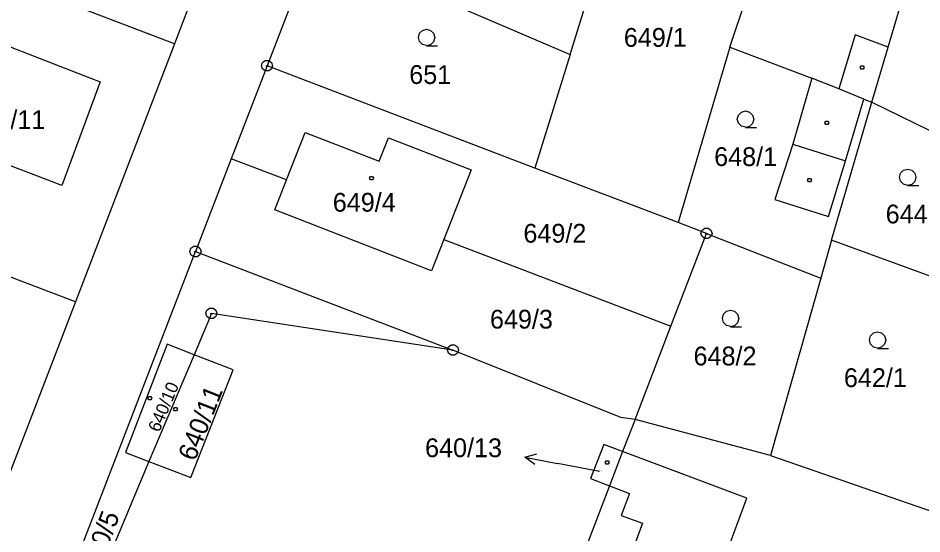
# Model space of a CAD drawing. Extents: x -759060 to -757386, y -1172273 to -1170948.
# Drawn here: x -758121.7 to -758040, y -1171296.1 to -1171249.4 of the extents above; entities that cross this region are included whole.
import ezdxf

# ---------------------------------------------------------------- set-up
doc = ezdxf.new("R2010")
doc.units = 0
for name, color, linetype in [('Vrstva 1', 7, 'Continuous'), ('Vrstva 12', 7, 'Continuous'), ('Vrstva 2', 7, 'Continuous'), ('Vrstva 3', 7, 'Continuous'), ('Vrstva 4', 7, 'Continuous'), ('Vrstva 5', 7, 'Continuous'), ('Vrstva 7', 7, 'Continuous'), ('Vrstva 8', 7, 'Continuous')]:
    doc.layers.add(name, color=color, linetype=linetype)

msp = doc.modelspace()

# ---------------------------------------------------------------- linework, layer by layer
at = {"layer": 'Vrstva 1'}
for p, q in [((-758084.37, -1171215.28), (-758099.2, -1171253.75)), ((-758071.82, -1171252.72), (-758063.29, -1171225.21)), ((-758098.72, -1171228.44), (-758107.56, -1171251.77)), ((-758043.08, -1171252.05), (-758039.35, -1171239.51)), ((-758107.56, -1171251.77), (-758135.53, -1171241.06)), ((-758057.4, -1171252.05), (-758054.82, -1171244.39)), ((-758090.57, -1171244.68), (-758071.82, -1171252.72)), ((-758107.56, -1171251.77), (-758116.52, -1171275.1)), ((-758122.42, -1171252.04), (-758115.22, -1171254.83)), ((-758071.82, -1171252.72), (-758075, -1171262.99)), ((-758057.4, -1171252.05), (-758062.05, -1171267.93)), ((-758057.4, -1171252.05), (-758049.98, -1171254.87)), ((-758044.56, -1171257.04), (-758043.08, -1171252.05)), ((-758099.2, -1171253.75), (-758102.44, -1171262.15)), ((-758075, -1171262.99), (-758099.2, -1171253.75)), ((-758114.28, -1171255.19), (-758117.74, -1171264.58)), ((-758115.22, -1171254.83), (-758114.28, -1171255.19)), ((-758049.98, -1171254.87), (-758051.7, -1171260.84)), ((-758046.92, -1171262.34), (-758045.28, -1171256.75)), ((-758045.28, -1171256.75), (-758044.56, -1171257.04)), ((-758048.21, -1171269.53), (-758044.56, -1171257.04)), ((-758044.56, -1171257.04), (-758033.42, -1171262.46)), ((-758118.67, -1171264.22), (-758130.07, -1171259.83)), ((-758097.44, -1171264.06), (-758095.77, -1171259.77)), ((-758095.77, -1171259.77), (-758089.07, -1171262.37)), ((-758089.07, -1171262.37), (-758088.24, -1171260.25)), ((-758088.24, -1171260.25), (-758080.77, -1171263.14)), ((-758051.7, -1171260.84), (-758053.32, -1171265.85)), ((-758102.44, -1171262.15), (-758105.67, -1171270.55)), ((-758097.44, -1171264.06), (-758102.44, -1171262.15)), ((-758048.46, -1171267.39), (-758046.92, -1171262.34)), ((-758080.77, -1171263.14), (-758083.24, -1171269.47)), ((-758062.05, -1171267.93), (-758075, -1171262.99)), ((-758117.74, -1171264.58), (-758118.67, -1171264.22)), ((-758098.49, -1171266.76), (-758097.44, -1171264.06)), ((-758116.52, -1171275.1), (-758144.5, -1171264.39)), ((-758053.32, -1171265.85), (-758048.46, -1171267.39)), ((-758084.33, -1171272.28), (-758098.49, -1171266.76)), ((-758059.49, -1171268.91), (-758062.05, -1171267.93)), ((-758062.71, -1171277.3), (-758059.49, -1171268.91)), ((-758059.49, -1171268.91), (-758049.17, -1171272.94)), ((-758083.24, -1171269.47), (-758084.33, -1171272.28)), ((-758083.24, -1171269.47), (-758062.71, -1171277.3)), ((-758048.21, -1171269.53), (-758049.17, -1171272.94)), ((-758037.2, -1171273.53), (-758048.21, -1171269.53)), ((-758118.62, -1171304.17), (-758105.67, -1171270.55)), ((-758105.67, -1171270.55), (-758082.4, -1171279.45)), ((-758049.17, -1171272.94), (-758053.7, -1171288.99)), ((-758116.52, -1171275.1), (-758125.5, -1171298.45)), ((-758104.23, -1171276.14), (-758105.8, -1171279.87)), ((-758082.4, -1171279.45), (-758104.23, -1171276.14)), ((-758065.95, -1171285.74), (-758062.71, -1171277.3)), ((-758108.22, -1171278.93), (-758112, -1171288.71)), ((-758105.8, -1171279.87), (-758108.22, -1171278.93)), ((-758067.22, -1171285.56), (-758082.4, -1171279.45)), ((-758105.8, -1171279.87), (-758109.87, -1171289.53)), ((-758102.26, -1171281.24), (-758105.8, -1171279.87)), ((-758106.09, -1171290.99), (-758102.26, -1171281.24)), ((-758065.95, -1171285.74), (-758067.22, -1171285.56)), ((-758065.95, -1171285.74), (-758067.07, -1171288.64)), ((-758053.7, -1171288.99), (-758065.95, -1171285.74)), ((-758112, -1171288.71), (-758109.87, -1171289.53)), ((-758068.78, -1171287.99), (-758069.97, -1171291.07)), ((-758067.07, -1171288.64), (-758068.78, -1171287.99)), ((-758067.07, -1171288.64), (-758068.26, -1171291.73)), ((-758055.84, -1171292.86), (-758067.07, -1171288.64)), ((-758109.87, -1171289.53), (-758115.76, -1171303.61)), ((-758109.87, -1171289.53), (-758106.09, -1171290.99)), ((-758053.7, -1171288.99), (-758017.68, -1171301.49)), ((-758069.97, -1171291.07), (-758068.26, -1171291.73)), ((-758068.26, -1171291.73), (-758070.29, -1171297.01)), ((-758066.98, -1171322.4), (-758055.84, -1171292.86))]:
    msp.add_line(p, q, dxfattribs=at)
at = {"layer": 'Vrstva 12'}
for p, q in [((-758122.42, -1171252.04), (-758115.22, -1171254.83)), ((-758114.28, -1171255.19), (-758117.74, -1171264.58)), ((-758115.22, -1171254.83), (-758114.28, -1171255.19)), ((-758118.67, -1171264.22), (-758130.07, -1171259.83)), ((-758097.44, -1171264.06), (-758095.77, -1171259.77)), ((-758095.77, -1171259.77), (-758089.07, -1171262.37)), ((-758089.07, -1171262.37), (-758088.24, -1171260.25)), ((-758088.24, -1171260.25), (-758080.77, -1171263.14)), ((-758080.77, -1171263.14), (-758083.24, -1171269.47)), ((-758117.74, -1171264.58), (-758118.67, -1171264.22)), ((-758098.49, -1171266.76), (-758097.44, -1171264.06)), ((-758084.33, -1171272.28), (-758098.49, -1171266.76)), ((-758083.24, -1171269.47), (-758084.33, -1171272.28)), ((-758108.22, -1171278.93), (-758112, -1171288.71)), ((-758105.8, -1171279.87), (-758108.22, -1171278.93)), ((-758102.26, -1171281.24), (-758105.8, -1171279.87)), ((-758106.09, -1171290.99), (-758102.26, -1171281.24)), ((-758112, -1171288.71), (-758109.87, -1171289.53)), ((-758068.78, -1171287.99), (-758069.97, -1171291.07)), ((-758067.07, -1171288.64), (-758068.78, -1171287.99)), ((-758055.84, -1171292.86), (-758067.07, -1171288.64)), ((-758109.87, -1171289.53), (-758106.09, -1171290.99)), ((-758069.97, -1171291.07), (-758068.26, -1171291.73)), ((-758068.26, -1171291.73), (-758066.46, -1171292.41)), ((-758066.46, -1171292.41), (-758067.21, -1171294.4)), ((-758066.98, -1171322.4), (-758055.84, -1171292.86)), ((-758067.21, -1171294.4), (-758065.27, -1171295.12)), ((-758065.27, -1171295.12), (-758068.76, -1171304.43))]:
    msp.add_line(p, q, dxfattribs=at)
at = {"layer": 'Vrstva 3'}
for points in [[(-758084.78, -1171251.92), (-758085.16, -1171251.82), (-758085.43, -1171251.55), (-758085.53, -1171251.18), (-758085.43, -1171250.81), (-758085.16, -1171250.54), (-758084.79, -1171250.44), (-758084.42, -1171250.54), (-758084.15, -1171250.81), (-758084.05, -1171251.19), (-758084.15, -1171251.57), (-758084.42, -1171251.84), (-758084.8, -1171251.94), (-758083.8, -1171251.94)], [(-758055.96, -1171259.31), (-758056.34, -1171259.21), (-758056.61, -1171258.94), (-758056.71, -1171258.57), (-758056.61, -1171258.2), (-758056.34, -1171257.93), (-758055.97, -1171257.83), (-758055.6, -1171257.93), (-758055.33, -1171258.2), (-758055.23, -1171258.58), (-758055.33, -1171258.96), (-758055.6, -1171259.23), (-758055.98, -1171259.33), (-758054.98, -1171259.33)], [(-758041.3, -1171264.56), (-758041.68, -1171264.46), (-758041.95, -1171264.19), (-758042.05, -1171263.82), (-758041.95, -1171263.45), (-758041.68, -1171263.18), (-758041.31, -1171263.08), (-758040.94, -1171263.18), (-758040.67, -1171263.45), (-758040.57, -1171263.83), (-758040.67, -1171264.21), (-758040.94, -1171264.48), (-758041.32, -1171264.58), (-758040.32, -1171264.58)], [(-758057.31, -1171277.33), (-758057.69, -1171277.23), (-758057.96, -1171276.96), (-758058.06, -1171276.59), (-758057.96, -1171276.22), (-758057.69, -1171275.95), (-758057.32, -1171275.85), (-758056.95, -1171275.95), (-758056.68, -1171276.22), (-758056.58, -1171276.6), (-758056.68, -1171276.98), (-758056.95, -1171277.25), (-758057.33, -1171277.35), (-758056.33, -1171277.35)], [(-758044.03, -1171279.28), (-758044.41, -1171279.18), (-758044.68, -1171278.91), (-758044.78, -1171278.54), (-758044.68, -1171278.17), (-758044.41, -1171277.9), (-758044.04, -1171277.8), (-758043.67, -1171277.9), (-758043.4, -1171278.17), (-758043.3, -1171278.55), (-758043.4, -1171278.93), (-758043.67, -1171279.2), (-758044.05, -1171279.3), (-758043.05, -1171279.3)]]:
    msp.add_lwpolyline(points, dxfattribs=at)
at = {"layer": 'Vrstva 4'}
for p, q in [((-758046.06, -1171250.96), (-758047.55, -1171255.84)), ((-758043.08, -1171252.05), (-758046.06, -1171250.96)), ((-758047.55, -1171255.84), (-758049.98, -1171254.87)), ((-758045.28, -1171256.75), (-758047.55, -1171255.84)), ((-758051.7, -1171260.84), (-758046.92, -1171262.34)), ((-758068.26, -1171291.73), (-758066.46, -1171292.41)), ((-758066.46, -1171292.41), (-758067.21, -1171294.4)), ((-758067.21, -1171294.4), (-758065.27, -1171295.12)), ((-758065.27, -1171295.12), (-758068.76, -1171304.43))]:
    msp.add_line(p, q, dxfattribs=at)
at = {"layer": 'Vrstva 5'}
for points in [[(-758045.35, -1171253.74), (-758045.26, -1171253.89), (-758045.35, -1171254.04), (-758045.53, -1171254.04), (-758045.62, -1171253.89), (-758045.53, -1171253.74)], [(-758048.54, -1171258.76), (-758048.45, -1171258.91), (-758048.54, -1171259.06), (-758048.72, -1171259.06), (-758048.81, -1171258.91), (-758048.72, -1171258.76)], [(-758089.66, -1171263.75), (-758089.57, -1171263.9), (-758089.66, -1171264.05), (-758089.84, -1171264.05), (-758089.93, -1171263.9), (-758089.84, -1171263.75)], [(-758050.1, -1171263.94), (-758050.01, -1171264.09), (-758050.1, -1171264.24), (-758050.28, -1171264.24), (-758050.37, -1171264.09), (-758050.28, -1171263.94)], [(-758109.71, -1171283.65), (-758109.62, -1171283.8), (-758109.71, -1171283.95), (-758109.89, -1171283.95), (-758109.98, -1171283.8), (-758109.89, -1171283.65)], [(-758107.39, -1171284.64), (-758107.3, -1171284.79), (-758107.39, -1171284.94), (-758107.57, -1171284.94), (-758107.66, -1171284.79), (-758107.57, -1171284.64)], [(-758068.37, -1171289.46), (-758068.28, -1171289.61), (-758068.37, -1171289.76), (-758068.55, -1171289.76), (-758068.64, -1171289.61), (-758068.55, -1171289.46)]]:
    msp.add_lwpolyline(points, close=True, dxfattribs=at)
at = {"layer": 'Vrstva 7'}
for p in [(-758075.907, -1171289.137), (-758069.16, -1171290.43)]:
    msp.add_line(p, (-758072.96, -1171289.7), dxfattribs=at)
msp.add_lwpolyline([(-758075.018, -1171289.816), (-758075.907, -1171289.137), (-758074.831, -1171288.834)], dxfattribs=at)
at = {"layer": 'Vrstva 8'}
for p, q in [((-758099.32, -1171253.75), (-758099.08, -1171253.75)), ((-758059.61, -1171268.91), (-758059.37, -1171268.91)), ((-758105.79, -1171270.55), (-758105.55, -1171270.55)), ((-758104.35, -1171276.14), (-758104.11, -1171276.14)), ((-758082.52, -1171279.45), (-758082.28, -1171279.45))]:
    msp.add_line(p, q, dxfattribs=at)
for points in [[(-758099.05, -1171253.27), (-758098.8, -1171253.45), (-758098.7, -1171253.74), (-758098.8, -1171254.03), (-758099.05, -1171254.21), (-758099.36, -1171254.21), (-758099.61, -1171254.03), (-758099.71, -1171253.74), (-758099.61, -1171253.45), (-758099.36, -1171253.27)], [(-758059.34, -1171268.43), (-758059.09, -1171268.61), (-758058.99, -1171268.9), (-758059.09, -1171269.19), (-758059.34, -1171269.37), (-758059.65, -1171269.37), (-758059.9, -1171269.19), (-758060, -1171268.9), (-758059.9, -1171268.61), (-758059.65, -1171268.43)], [(-758105.52, -1171270.07), (-758105.27, -1171270.25), (-758105.17, -1171270.54), (-758105.27, -1171270.83), (-758105.52, -1171271.01), (-758105.83, -1171271.01), (-758106.08, -1171270.83), (-758106.18, -1171270.54), (-758106.08, -1171270.25), (-758105.83, -1171270.07)], [(-758104.08, -1171275.66), (-758103.83, -1171275.84), (-758103.73, -1171276.13), (-758103.83, -1171276.42), (-758104.08, -1171276.6), (-758104.39, -1171276.6), (-758104.64, -1171276.42), (-758104.74, -1171276.13), (-758104.64, -1171275.84), (-758104.39, -1171275.66)], [(-758082.25, -1171278.97), (-758082, -1171279.15), (-758081.9, -1171279.44), (-758082, -1171279.73), (-758082.25, -1171279.91), (-758082.56, -1171279.91), (-758082.81, -1171279.73), (-758082.91, -1171279.44), (-758082.81, -1171279.15), (-758082.56, -1171278.97)]]:
    msp.add_lwpolyline(points, close=True, dxfattribs=at)

# ---------------------------------------------------------------- texts
at = {"layer": 'Vrstva 2'}
for s, height, p in [('649/1', 1.7, (-758066.965, -1171252.03)), ('651', 1.7, (-758086.353, -1171255.39)), ('633/11', 1.7, (-758126.19, -1171259.47)), ('648/1', 1.7, (-758058.802, -1171262.81)), ('649/4', 1.7, (-758093.263, -1171266.94)), ('644', 1.7, (-758043.304, -1171268)), ('649/2', 1.7, (-758076.037, -1171269.74)), ('649/3', 1.7, (-758079.06, -1171277.51)), ('648/2', 1.7, (-758060.664, -1171280.84)), ('642/1', 1.7, (-758047.079, -1171282.8)), ('640/13', 0.1, (-758069.389, -1171290.43))]:
    msp.add_text(s, height=height, dxfattribs=at).set_placement(p)
for s, height, rotation, p in [('640/10', 1.14, 67.03606, (-758108.951, -1171286.954)), ('640/11', 1.7, 68.41116, (-758105.721, -1171289.581)), ('640/5', 1.7, 69.2706, (-758114.501, -1171299.74))]:
    msp.add_text(s, height=height, rotation=rotation, dxfattribs=at).set_placement(p)
at = {"layer": 'Vrstva 7'}
msp.add_text('640/13', height=1.7, dxfattribs=at).set_placement((-758084.924, -1171289.14))

doc.saveas('drawing.dxf')
